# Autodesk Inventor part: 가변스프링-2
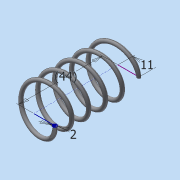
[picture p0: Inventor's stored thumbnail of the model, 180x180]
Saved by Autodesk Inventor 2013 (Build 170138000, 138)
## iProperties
Created: 2020-07
Part Number: 가변스프링-2
Material: 스테인리스강
Document SubType Name: Modeling
Designer: dgall
Density: 8.08 g/cm^3
Mass: 8.67687 g
Surface Area: 21.7206 cm^2
Volume: 1.07387 cm^3
Author: dgall
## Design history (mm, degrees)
sketch "스케치1"
  geometry: L1 (11, 0)-(0, 0); L2 (0, 0)-(0, 39.108); L3 (0, 39.108)-(11, 39.108); C1 r 1 at (11, 0)
  constraints: 6 end point, 2 horizontal, 1 centre point, 1 coincident, 1 perpendicular, 1 vertical alignment
  dimensions: "d0" = 2 diameter of C1; "d2" = 39.10829 distance of L1.end L2.end (derived); "d3" = 11 distance of L2.end L3.end
feature "코일1" pitch "d4" = 10; turns "d6" = 5; dims "d5" = 39.10829 (= d2), "d7" = 0, angle "d8" = 90 deg, angle "d9" = 90 deg, "d10" = 0, "d11" = 0
node "작업 평면2"
  node "작업 평면1"
feature "분할1"
feature "분할2"
node "솔리드1"
other parameters: "d12" = 0, "d13" = 0
